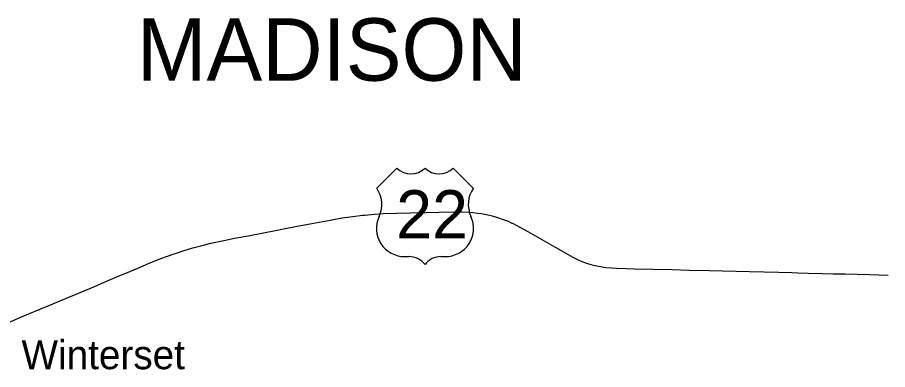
# Model space of a CAD drawing. Extents: x -29.6 to 34, y 0 to 22.
# Drawn here: x -15.9 to -13.674, y 8.137 to 9.039 of the extents above; entities that cross this region are included whole.
import ezdxf

# ---------------------------------------------------------------- set-up
doc = ezdxf.new("R2010")
doc.units = 0
for name, color, linetype in [('GM_X_Township_Road', 7, 'Continuous'), ('GM_X_Township_Text', 7, 'Continuous'), ('GM_X_Unincorporated_Text', 7, 'Continuous'), ('GM_X_US_Route', 7, 'Continuous'), ('GM_X_US_Shield', 7, 'Continuous')]:
    doc.layers.add(name, color=color, linetype=linetype)

msp = doc.modelspace()

# ---------------------------------------------------------------- linework, layer by layer
at = {"layer": 'GM_X_Township_Road'}
msp.add_line((-15.8431, 8.291), (-15.8407, 8.2921), dxfattribs=at)
at = {"layer": 'GM_X_US_Route'}
msp.add_line((-15.8431, 8.291), (-15.8407, 8.2921), dxfattribs=at)
for points in [[(-15.8407, 8.2921), (-15.8275, 8.2977), (-15.7888, 8.3139), (-15.7683, 8.3224), (-15.7398, 8.3342), (-15.7044, 8.3491), (-15.6857, 8.3572), (-15.6438, 8.3749), (-15.6126, 8.3878), (-15.5924, 8.3964), (-15.5651, 8.4081), (-15.5332, 8.4209), (-15.5186, 8.4264), (-15.4964, 8.434), (-15.493, 8.4352), (-15.4733, 8.4416), (-15.4513, 8.4484), (-15.4306, 8.4541), (-15.4055, 8.4602), (-15.3719, 8.4677), (-15.3451, 8.473), (-15.3102, 8.4797), (-15.2707, 8.4871), (-15.2398, 8.4931), (-15.2198, 8.4969), (-15.1883, 8.5029), (-15.1471, 8.5107), (-15.1002, 8.5197), (-15.0692, 8.5251), (-15.0421, 8.5291), (-15.0172, 8.5321), (-15.0117, 8.5326)], [(-15.0117, 8.5326), (-14.9876, 8.5348), (-14.9643, 8.5363), (-14.9299, 8.5376), (-14.895, 8.5385), (-14.8542, 8.5394), (-14.8216, 8.54), (-14.782, 8.5409), (-14.7628, 8.5409), (-14.7459, 8.5402), (-14.7342, 8.5392), (-14.723, 8.5376)], [(-14.723, 8.5376), (-14.7137, 8.5363), (-14.7089, 8.5354), (-14.7002, 8.5337), (-14.686, 8.5303), (-14.672, 8.5263), (-14.6576, 8.5215), (-14.645, 8.5167), (-14.635, 8.5121)], [(-14.635, 8.5121), (-14.6333, 8.5114), (-14.6146, 8.5018), (-14.5942, 8.4905), (-14.5287, 8.4525), (-14.4973, 8.4346), (-14.4794, 8.4249), (-14.4669, 8.4187), (-14.4563, 8.414), (-14.4444, 8.4096), (-14.4328, 8.4059), (-14.4226, 8.4033), (-14.4084, 8.4006), (-14.3952, 8.3986), (-14.3807, 8.3972), (-14.3674, 8.3965), (-14.3418, 8.3956), (-14.3214, 8.3949), (-14.2754, 8.3939), (-14.2255, 8.3928), (-14.1819, 8.3918), (-14.1306, 8.3905), (-14.027, 8.3878), (-13.953, 8.386), (-13.9193, 8.3851), (-13.9036, 8.3847), (-13.8774, 8.3841), (-13.8407, 8.3832), (-13.8134, 8.3824), (-13.7825, 8.3819), (-13.7202, 8.3799), (-13.6725, 8.379)], [(-15.9782, 8.2309), (-15.9769, 8.232), (-15.9763, 8.2325), (-15.9729, 8.235), (-15.9708, 8.2363), (-15.9688, 8.2374), (-15.9642, 8.2399), (-15.9554, 8.2438), (-15.9479, 8.2471), (-15.9458, 8.248), (-15.9378, 8.2512), (-15.9304, 8.2544), (-15.9219, 8.2579), (-15.9183, 8.2594), (-15.8977, 8.2681), (-15.8952, 8.2691), (-15.8833, 8.2741), (-15.8691, 8.2801), (-15.8445, 8.2904), (-15.8431, 8.291)]]:
    msp.add_lwpolyline(points, dxfattribs=at)
at = {"layer": 'GM_X_US_Shield'}
for p, q in [((-14.9295, 8.6529), (-14.981, 8.6014)), ((-14.7338, 8.6014), (-14.7853, 8.6529)), ((-14.9089, 8.4263), (-14.8986, 8.4263)), ((-14.8162, 8.4263), (-14.8059, 8.4263))]:
    msp.add_line(p, q, dxfattribs=at)
for centre, radius, start, end in [((-14.8934, 8.6897), 0.0515, 225.573, 314.427), ((-14.8213, 8.6897), 0.0515, 225.573, 314.427), ((-15.04, 8.5601), 0.0721, 334.5471, 35.0009), ((-14.6747, 8.5601), 0.0721, 144.9991, 205.4529), ((-14.9097, 8.4984), 0.0721, 154.8319, 270.6383), ((-14.8051, 8.4984), 0.0721, 269.3617, 25.1681), ((-14.8986, 8.3748), 0.0515, 36.8699, 90), ((-14.8162, 8.3748), 0.0515, 90, 143.1301)]:
    msp.add_arc(centre, radius, start, end, dxfattribs=at)

# ---------------------------------------------------------------- texts
at = {"layer": 'GM_X_Township_Text'}
msp.add_text('MADISON', height=0.1598, rotation=0, dxfattribs=at).set_placement((-15.5943, 8.8767))
at = {"layer": 'GM_X_Unincorporated_Text'}
msp.add_text('Winterset', height=0.07404, rotation=0, dxfattribs=at).set_placement((-15.8896, 8.1377))
at = {"layer": 'GM_X_US_Shield'}
msp.add_text('22', height=0.1236, dxfattribs=at).set_placement((-14.9312, 8.4727))

doc.saveas('drawing.dxf')
